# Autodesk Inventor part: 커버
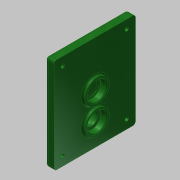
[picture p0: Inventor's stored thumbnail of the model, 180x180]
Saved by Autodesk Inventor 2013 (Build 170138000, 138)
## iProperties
Created: 2016-02
Part Number: 커버
Material: 일반
Document SubType Name: Modeling
Designer: mduedu
Density: 2.71 g/cm^3
Author: mduedu
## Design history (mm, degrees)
sketch "스케치1"
  geometry: L1 (63, 47)-(-47, 47); L2 (-47, 47)-(-47, -47); L3 (-47, -47)-(63, -47); L4 (63, -47)-(63, 47); 2 further points
  constraints: 8 end point, 2 parallel, 1 horizontal, 1 horizontal alignment, 1 midpoint, 1 perpendicular
  dimensions: "d102" = 94 distance of L3.end L1.start; "d104" = 47 distance from line of L2 point (0, 0); "d105" = 110 distance of L1.start L1.end
extrude "돌출1" new body sketch "스케치1" distance "d1" = 10; taper "d2" = 0 deg
sketch "스케치2"
  geometry: C1 r 14 at (0, 11); 1 further point
  constraints: 1 centre point, 1 vertical alignment
  dimensions: "d3" = 28 diameter of C1; "d6" = 11 distance of C1.centre point (0, 0)
extrude "돌출2" join sketch "스케치2" distance "d7" = 3; taper "d8" = 0 deg
sketch "스케치3"
  geometry: C1 r 14 at (0, -20); 1 further point
  constraints: 1 centre point, 1 vertical alignment
  dimensions: "d9" = 28 diameter of C1; "d10" = 20 distance of C1.centre point (0, 0)
extrude "돌출3" join sketch "스케치3" distance "d11" = 3; taper "d12" = 0 deg
hole "구멍1" diameter "d15" = 22; stored, may be unused: countersink angle "d19" = 90 deg, drill point angle "d21" = 0 deg; dims "d13" = 10, "d14" = 10, "d16" = 6, "d17" = 4, "d18" = 2, "d20" = 7
hole "구멍2" diameter "d24" = 18; stored, may be unused: countersink angle "d28" = 90 deg, drill point angle "d30" = 0 deg; dims "d22" = 10, "d23" = 10, "d25" = 6, "d26" = 4, "d27" = 2, "d29" = 1
hole "구멍3" diameter "d33" = 22; stored, may be unused: countersink angle "d37" = 90 deg, drill point angle "d39" = 0 deg; dims "d34" = 6, "d35" = 4, "d36" = 2, "d38" = 7, "d73" = 10, "d74" = 10
sketch "스케치4"
  geometry: C1 r 14 at (0, -20) reference; C2 r 18 at (0, -20); 1 further point
  constraints: 1 centre point, 1 coincident
  dimensions: "d40" = 36 diameter of C2
extrude "돌출4" join sketch "스케치4" distance "d41" = 4; taper "d42" = 0 deg
hole "구멍4" diameter "d45" = 22; stored, may be unused: countersink angle "d49" = 90 deg, drill point angle "d51" = 0 deg; dims "d43" = 10, "d44" = 10, "d46" = 6, "d47" = 4, "d48" = 2, "d50" = 7
hole "구멍5" diameter "d54" = 15; stored, may be unused: countersink angle "d58" = 90 deg, drill point angle "d60" = 0 deg; dims "d52" = 10, "d53" = 10, "d55" = 6, "d56" = 4, "d57" = 2, "d59" = 7
fillet "모깎기1" dims "d61" = 0.3
fillet "모깎기2" dims "d62" = 2
chamfer "모따기1" distance "d63" = 1; stored, may be unused: second distance "d64" = 2, angle "d65" = 45 deg
fillet "모깎기6" dims "d88" = 2
fillet "모깎기4" dims "d75" = 2
sketch "스케치9"
  geometry: L1 (47, 63)-(47, -47) reference; L2 (-47, 63)-(47, 63) reference; L3 (-47, -47)-(-47, 63) reference; L4 (47, -47)-(-47, -47) reference; L5 (37, 53)-(37, -37); L6 (37, -37)-(-37, -37); L7 (-37, -37)-(-37, 53); L8 (-37, 53)-(37, 53); C1 r 20 at (0, -20) reference; 5 further points
  constraints: 8 end point, 4 coincident, 3 other
  dimensions: "d107" = 10 distance between parallel lines of L8 L2
hole "구멍7" sketch "스케치9" at (-37, 53), (37, 53), (37, -37), (-37, -37) diameter "d108" = 4.5; stored, may be unused: countersink angle "d112" = 90 deg, drill point angle "d114" = 118 deg; dims "d109" = 6, "d110" = 8, "d111" = 4.6, "d113" = 8
fillet "모깎기8" dims "d106" = 3
fillet "모깎기9" dims "d115" = 3
node "솔리드1"
node "투영된 루프2"
